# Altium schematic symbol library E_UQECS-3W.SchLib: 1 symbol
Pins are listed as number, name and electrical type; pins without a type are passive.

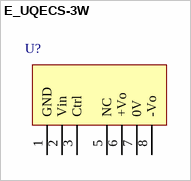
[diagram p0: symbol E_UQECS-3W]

## E_UQECS-3W
designator U?
footprint E_UQECS-3W
pins: 1 GND, 2 Vin, 3 Ctrl, 5 NC, 6 +Vo, 7 0V, 8 -Vo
